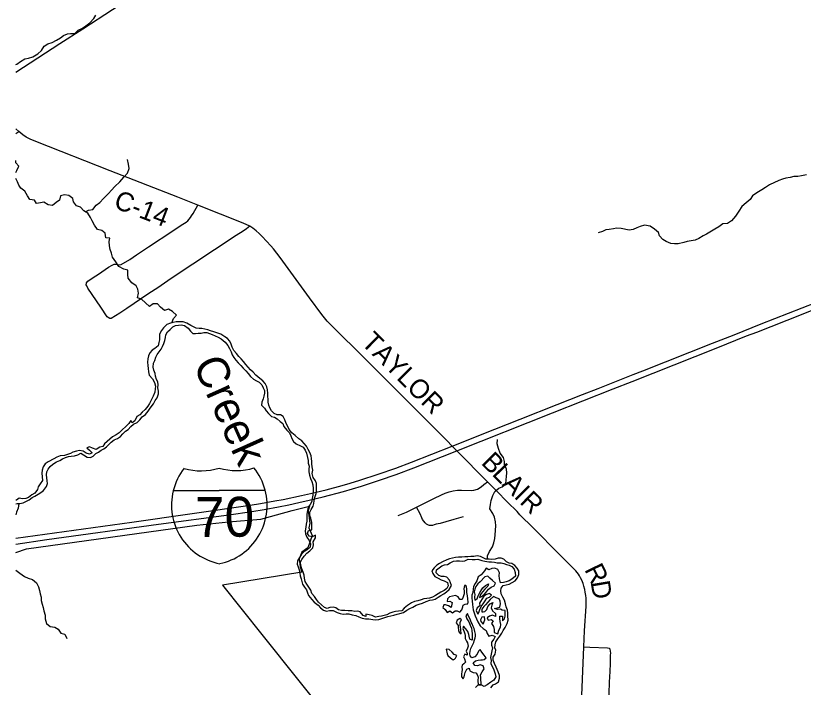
# Model space of a CAD drawing. Extents: x 114843 to 284848, y 317643 to 566895.
# Drawn here: x 114843 to 127204, y 384376 to 394917 of the extents above; entities that cross this region are included whole.
import ezdxf

# ---------------------------------------------------------------- set-up
doc = ezdxf.new("R2010")
doc.units = 0
for name, color, linetype in [('GM_X_Corporation', 7, 'Continuous'), ('GM_X_County_Road', 7, 'Continuous'), ('GM_X_County_Road_Text', 7, 'Continuous'), ('GM_X_Interstate_Location', 7, 'Continuous'), ('GM_X_Interstate_Route', 7, 'Continuous'), ('GM_X_Interstate_Shield', 7, 'Continuous'), ('GM_X_Major_River', 7, 'Continuous'), ('GM_X_Major_River_Text', 7, 'Continuous'), ('GM_X_Minor_Lake', 7, 'Continuous'), ('GM_X_Minor_River', 7, 'Continuous'), ('GM_X_Township_Road', 7, 'Continuous')]:
    doc.layers.add(name, color=color, linetype=linetype)

msp = doc.modelspace()

# ---------------------------------------------------------------- linework, layer by layer
at = {"layer": 'GM_X_Corporation'}
msp.add_lwpolyline([(114843, 386490), (115013, 386549), (117687, 386922), (118185, 386971), (118689, 387015), (119180, 387148), (119453, 387216), (119431, 387149), (119458, 386954), (119444, 386879), (119495, 386757), (119430, 386567), (119336, 386495), (119292, 386394), (119309, 386265), (119336, 386184), (118089, 385981), (118705, 385204), (119847, 383776)], dxfattribs=at)
at = {"layer": 'GM_X_County_Road'}
msp.add_line((114891, 393098), (114843, 393144), dxfattribs=at)
for points in [[(114843, 394030), (115537, 394481), (115896, 394713), (116363, 395017), (116608, 395180), (117070, 395482), (117905, 396014), (118844, 396617), (119342, 396934), (119699, 397166), (120059, 397395), (120571, 397725), (121846, 398557), (122838, 399201), (123440, 399595), (124015, 399975), (124071, 400009), (124123, 400049), (124177, 400087), (124205, 400104), (124322, 400169)], [(118515, 391612), (118461, 391640), (118386, 391672), (118055, 391803), (117699, 391946), (117386, 392070), (116324, 392482), (115157, 392941), (115067, 392979), (115037, 392993), (115008, 393009), (114954, 393046), (114891, 393098)], [(122246, 387600), (121765, 388088), (121694, 388161), (121607, 388250), (121545, 388311), (121076, 388785), (120288, 389572), (119845, 390009), (119731, 390124), (119687, 390175), (119646, 390227), (119452, 390491), (118991, 391123), (118887, 391256), (118845, 391306), (118780, 391380), (118713, 391452), (118666, 391498), (118618, 391542), (118592, 391563), (118565, 391581), (118515, 391612)], [(123758, 385008), (123770, 385259), (123794, 385651), (123796, 385717), (123794, 385777), (123791, 385815), (123782, 385871), (123774, 385911), (123759, 385965), (123747, 386006), (123726, 386057), (123708, 386096), (123692, 386124), (123674, 386151), (123633, 386202), (123473, 386366), (123264, 386574), (123080, 386761), (123010, 386829), (122965, 386877), (122757, 387085), (122712, 387133), (122562, 387280), (122388, 387458), (122246, 387600)], [(123665, 382836), (123691, 383364), (123758, 385008)]]:
    msp.add_lwpolyline(points, dxfattribs=at)
at = {"layer": 'GM_X_Interstate_Route'}
for points in [[(114843, 386624), (115332, 386693), (117085, 386935), (118190, 387084), (118547, 387136), (118741, 387168), (118967, 387209), (119128, 387241), (119288, 387276), (119448, 387311), (119671, 387365), (119988, 387450), (120271, 387534), (120552, 387625), (120816, 387718), (121094, 387822), (121765, 388088), (123267, 388684), (124218, 389058), (124517, 389177), (125835, 389697), (126314, 389890), (126476, 389950), (127177, 390227), (127765, 390461)], [(114843, 386718), (116664, 386970), (118524, 387234), (118686, 387261), (118912, 387300), (119041, 387325), (119330, 387384), (119471, 387416), (119713, 387477), (119966, 387545), (120092, 387581), (120246, 387628), (120530, 387720), (120809, 387816), (121054, 387908), (121694, 388161), (122363, 388425), (122762, 388584), (123343, 388812), (123739, 388970), (123983, 389065), (124196, 389151), (124532, 389283), (124686, 389343), (125782, 389777), (126118, 389909), (126545, 390079), (127400, 390416)]]:
    msp.add_lwpolyline(points, dxfattribs=at)
at = {"layer": 'GM_X_Interstate_Shield'}
for p, q in [((117316, 387460), (118758, 387470)), ((118758, 387470), (117316, 387460)), ((118758, 387470), (117316, 387460))]:
    msp.add_line(p, q, dxfattribs=at)
for centre, start, end in [((118226, 387236), 142.0801, 166.2178), ((117754, 388711), 253.4202, 287.4021), ((118302, 388715), 253.4202, 287.4021), ((117851, 387234), 14.6045, 38.7422), ((118226, 387236), 166.2178, 258.8742), ((117851, 387234), 281.9481, 14.6045)]:
    msp.add_arc(centre, 938, start, end, dxfattribs=at)
at = {"layer": 'GM_X_Major_River'}
msp.add_line((122103, 384414), (122149, 384412), dxfattribs=at)
for points in [[(119355, 386182), (119335, 386236), (119320, 386288), (119312, 386338), (119336, 386383), (119370, 386435), (119414, 386479), (119458, 386517), (119504, 386565), (119518, 386609), (119510, 386657), (119550, 386721), (119546, 386761), (119494, 386737), (119448, 386747), (119422, 386791), (119440, 386837), (119492, 386849), (119492, 386961), (119476, 387028), (119458, 387074), (119460, 387122), (119482, 387166), (119512, 387216), (119520, 387262), (119528, 387304), (119540, 387354), (119556, 387416), (119564, 387468), (119566, 387516), (119562, 387572), (119546, 387616), (119510, 387669), (119494, 387729), (119504, 387785), (119498, 387837), (119493, 387881), (119489, 387921), (119485, 387969), (119479, 388011), (119459, 388059), (119435, 388107), (119407, 388159), (119371, 388203), (119333, 388244), (119289, 388274), (119227, 388330), (119179, 388368), (119137, 388420), (119117, 388460), (119087, 388518), (119067, 388572), (119039, 388624), (118997, 388650), (118949, 388654), (118897, 388673), (118859, 388715), (118831, 388761), (118816, 388803), (118806, 388849), (118804, 388895), (118802, 388943), (118800, 388993), (118794, 389043), (118782, 389093), (118756, 389145), (118720, 389187), (118676, 389222), (118610, 389276), (118570, 389320), (118528, 389360), (118490, 389402), (118454, 389444), (118416, 389488), (118380, 389530), (118344, 389570), (118306, 389614), (118268, 389662), (118240, 389713), (118222, 389761), (118203, 389807), (118167, 389849), (118123, 389877), (118061, 389917), (117999, 389941), (117951, 389955), (117901, 389971), (117857, 389985), (117811, 389997), (117765, 390005), (117723, 390009), (117677, 390011), (117633, 390032), (117591, 390056), (117531, 390090), (117471, 390110), (117411, 390110), (117361, 390112), (117315, 390102), (117273, 390092), (117217, 390068)], [(117217, 390068), (117161, 390018), (117129, 389976), (117101, 389916), (117097, 389872), (117097, 389830), (117091, 389786), (117079, 389735), (117025, 389693), (116985, 389669), (116949, 389627), (116925, 389579), (116915, 389529), (116911, 389479), (116915, 389425), (116923, 389377), (116927, 389325), (116939, 389275), (116991, 389215), (117019, 389161), (117037, 389102), (117031, 389058), (117025, 389010), (116999, 388946), (116941, 388830), (116915, 388788), (116877, 388734), (116829, 388692), (116791, 388653), (116745, 388626), (116711, 388560), (116669, 388525), (116651, 388562), (116618, 388518), (116576, 388476), (116510, 388414), (116468, 388368), (116418, 388336), (116360, 388308), (116320, 388268), (116276, 388234), (116234, 388198), (116208, 388156), (116163, 388144), (116107, 388107), (116049, 388130), (116003, 388150), (115959, 388132), (116003, 388100), (116045, 388055), (116001, 388033), (115949, 388051), (115901, 388080), (115843, 388094), (115797, 388080), (115741, 388064), (115701, 388044), (115653, 388028), (115611, 388016), (115539, 388008), (115489, 387988), (115441, 387964), (115353, 387912), (115303, 387884), (115271, 387838), (115259, 387783), (115255, 387735), (115257, 387679), (115261, 387621), (115229, 387571), (115193, 387523), (115185, 387481), (115143, 387423), (115095, 387395), (115045, 387357), (114999, 387339), (114951, 387333), (114897, 387343), (114857, 387315), (114843, 387311)], [(114843, 387256), (114863, 387261), (114905, 387263), (114961, 387273), (115011, 387295), (115053, 387319), (115101, 387353), (115145, 387377), (115193, 387405), (115235, 387433), (115281, 387467), (115325, 387527), (115339, 387573), (115337, 387617), (115333, 387663), (115325, 387709), (115329, 387755), (115353, 387797), (115385, 387840), (115427, 387878), (115483, 387914), (115533, 387936), (115575, 387960), (115623, 387982), (115669, 387996), (115715, 388002), (115763, 388010), (115817, 388026), (115863, 388052), (115909, 388023), (115966, 387989), (116016, 387983), (116058, 388003), (116102, 388045), (116144, 388067), (116186, 388099), (116228, 388119), (116270, 388151), (116342, 388224), (116388, 388258), (116440, 388280), (116486, 388312), (116522, 388356), (116566, 388396), (116610, 388424), (116652, 388468), (116694, 388504), (116748, 388530), (116792, 388576), (116826, 388622), (116882, 388660), (116924, 388712), (116952, 388756), (117006, 388824), (117031, 388876), (117063, 388920), (117085, 388982), (117083, 389022), (117071, 389074), (117081, 389122), (117075, 389169), (117051, 389209), (117039, 389259), (117031, 389303), (117011, 389351), (116999, 389399), (117005, 389461), (117025, 389507), (117043, 389555), (117063, 389599), (117093, 389641), (117127, 389683), (117149, 389725), (117167, 389773), (117183, 389818), (117193, 389868), (117199, 389910), (117225, 389956), (117267, 389992)], [(117267, 389992), (117311, 390034)], [(117311, 390034), (117351, 390056), (117399, 390060), (117441, 390064), (117491, 390056), (117551, 390012), (117585, 389967), (117623, 389927), (117667, 389931), (117709, 389933), (117751, 389933), (117795, 389945), (117841, 389943), (117883, 389927), (117927, 389913), (117971, 389893), (118019, 389873), (118065, 389843), (118129, 389791), (118170, 389741), (118196, 389693), (118224, 389643), (118242, 389594), (118264, 389550), (118296, 389510), (118332, 389468), (118374, 389426), (118414, 389384), (118454, 389344), (118492, 389302), (118530, 389256), (118576, 389212), (118622, 389188), (118664, 389163), (118704, 389123), (118728, 389077), (118746, 389035), (118746, 388991), (118738, 388945), (118726, 388903), (118704, 388849), (118702, 388803), (118746, 388757), (118773, 388715), (118811, 388673), (118855, 388628), (118903, 388618), (118945, 388592), (118991, 388546), (119035, 388514), (119051, 388468), (119097, 388410), (119141, 388372), (119159, 388324), (119175, 388282), (119201, 388234), (119243, 388198), (119311, 388167), (119353, 388143), (119387, 388099), (119405, 388049), (119421, 387985), (119431, 387937), (119435, 387895), (119447, 387849), (119445, 387801), (119442, 387757), (119452, 387703), (119472, 387655), (119490, 387606), (119508, 387556), (119514, 387496), (119510, 387442), (119506, 387392), (119498, 387340), (119488, 387294), (119464, 387246), (119432, 387202), (119420, 387148), (119412, 387094), (119412, 387032), (119410, 386983), (119404, 386935), (119396, 386891), (119384, 386833), (119392, 386785), (119412, 386733), (119450, 386679), (119472, 386627), (119464, 386577), (119416, 386533), (119370, 386509), (119330, 386463), (119296, 386411), (119268, 386363), (119258, 386310), (119278, 386268), (119291, 386218), (119301, 386168), (119307, 386124)], [(122460, 385930), (122494, 385974), (122540, 385986), (122586, 385994), (122636, 386018), (122682, 386048), (122718, 386096), (122742, 386146), (122740, 386202), (122714, 386246), (122676, 386289), (122628, 386317), (122586, 386323), (122544, 386343), (122504, 386385), (122462, 386401), (122414, 386401), (122366, 386389), (122318, 386379), (122274, 386387), (122224, 386389), (122178, 386405), (122136, 386431), (122084, 386437), (122032, 386431), (121986, 386427), (121938, 386425), (121890, 386421), (121846, 386419), (121792, 386417), (121748, 386415), (121696, 386401), (121652, 386393), (121608, 386375), (121544, 386343), (121496, 386321), (121452, 386291), (121412, 386251), (121376, 386205), (121388, 386163), (121422, 386117), (121474, 386087), (121522, 386063), (121570, 386049), (121618, 386019), (121632, 385967), (121610, 385924), (121566, 385894), (121518, 385866), (121476, 385842), (121430, 385814), (121386, 385790), (121340, 385774), (121294, 385768), (121248, 385764), (121206, 385750), (121154, 385734), (121100, 385722), (121054, 385700), (120994, 385660), (120940, 385618), (120902, 385576), (120852, 385572), (120802, 385564), (120762, 385554), (120714, 385538), (120666, 385514), (120624, 385502), (120582, 385494), (120542, 385484), (120488, 385478), (120438, 385500), (120388, 385514), (120340, 385525), (120340, 385484), (120294, 385503), (120249, 385561), (120207, 385571), (120165, 385567), (120121, 385575), (120059, 385577), (120011, 385579), (119957, 385579), (119911, 385591), (119869, 385621), (119823, 385633), (119775, 385629), (119733, 385611), (119687, 385629), (119641, 385671), (119595, 385709), (119565, 385753), (119531, 385799), (119493, 385846), (119473, 385898), (119445, 385946), (119411, 385992), (119387, 386038), (119375, 386088), (119369, 386136), (119355, 386182)], [(119307, 386124), (119323, 386078), (119333, 386034), (119345, 385992), (119377, 385948), (119409, 385904), (119425, 385860), (119437, 385818), (119491, 385755), (119529, 385713), (119589, 385665), (119625, 385621), (119673, 385585), (119719, 385569), (119767, 385579), (119823, 385579), (119887, 385549), (119937, 385533), (119985, 385525), (120029, 385529), (120073, 385527), (120123, 385515), (120183, 385501), (120230, 385483), (120282, 385460), (120334, 385450), (120384, 385448), (120448, 385438), (120490, 385436), (120544, 385442), (120588, 385456), (120634, 385472), (120682, 385488), (120778, 385508), (120830, 385522), (120870, 385532), (120928, 385552), (120980, 385586), (121030, 385612), (121076, 385634), (121128, 385662), (121174, 385682), (121230, 385698), (121284, 385722), (121342, 385742), (121382, 385750), (121424, 385760), (121474, 385792), (121516, 385814), (121560, 385844), (121602, 385872), (121648, 385908), (121682, 385973), (121668, 386015), (121652, 386059), (121612, 386105), (121568, 386113), (121526, 386113), (121482, 386129), (121444, 386173), (121448, 386217), (121490, 386253), (121530, 386283), (121574, 386299), (121620, 386305), (121664, 386329), (121712, 386355), (121760, 386359), (121806, 386359), (121852, 386355), (121894, 386363), (121944, 386385), (122008, 386381), (122054, 386379), (122096, 386389), (122160, 386365), (122206, 386353), (122268, 386345), (122310, 386345), (122356, 386337), (122402, 386331), (122462, 386327), (122504, 386321), (122546, 386305), (122588, 386295), (122632, 386271), (122666, 386230), (122680, 386178), (122686, 386120), (122632, 386074), (122586, 386046), (122542, 386030), (122498, 386022), (122452, 386016), (122434, 386078), (122432, 386132), (122438, 386174), (122412, 386223), (122364, 386247), (122314, 386239), (122270, 386219)], [(122270, 386219), (122228, 386243), (122202, 386201), (122148, 386143), (122104, 386109), (122078, 386048), (122054, 386006), (122028, 385960), (122022, 385914), (122016, 385864), (122000, 385822), (122000, 385774), (122006, 385732), (122010, 385676), (122020, 385632), (122024, 385592), (122036, 385546), (122056, 385496), (122077, 385449), (122097, 385403), (122131, 385341), (122181, 385299), (122229, 385267), (122241, 385221), (122269, 385179), (122319, 385191), (122369, 385173), (122345, 385129), (122313, 385083), (122311, 385037), (122325, 384993), (122317, 384949), (122305, 384894), (122297, 384844), (122303, 384796), (122301, 384750), (122349, 384650), (122367, 384588), (122381, 384542), (122349, 384486), (122301, 384454), (122241, 384412), (122195, 384390), (122149, 384412), (122103, 384414), (122059, 384374)], [(122376, 386008), (122328, 386050), (122286, 386088), (122252, 386122), (122208, 386108), (122132, 386032), (122094, 386002), (122064, 385958), (122050, 385914), (122036, 385872), (122050, 385832), (122044, 385788), (122050, 385744), (122066, 385753)], [(122066, 385753), (122088, 385766), (122104, 385812), (122122, 385852), (122142, 385892), (122176, 385936), (122214, 385972), (122262, 385998), (122252, 385962), (122204, 385916), (122168, 385874), (122136, 385830), (122124, 385786), (122156, 385800), (122196, 385834), (122232, 385874), (122262, 385914), (122306, 385946), (122352, 385966), (122376, 386008)], [(122301, 384368), (122335, 384414), (122375, 384432), (122421, 384462), (122435, 384516), (122435, 384560), (122415, 384620), (122383, 384690), (122357, 384748), (122339, 384802), (122339, 384850), (122369, 384896), (122377, 384957), (122365, 384997), (122367, 385043), (122381, 385087), (122409, 385135), (122441, 385177), (122475, 385227), (122495, 385269), (122525, 385315), (122555, 385377), (122573, 385431), (122567, 385495), (122569, 385539), (122563, 385585), (122539, 385638), (122533, 385686), (122517, 385742), (122488, 385792), (122464, 385844), (122456, 385890), (122460, 385930)], [(122289, 385838), (122278, 385846), (122232, 385830), (122192, 385806), (122166, 385762), (122136, 385722), (122122, 385696), (122126, 385656), (122084, 385624), (122068, 385582), (122098, 385524)], [(122098, 385524), (122114, 385550), (122130, 385598), (122148, 385646), (122180, 385688), (122212, 385732), (122236, 385772), (122280, 385788), (122310, 385822), (122289, 385838)], [(122409, 385214), (122427, 385273), (122451, 385317), (122459, 385361), (122449, 385409), (122439, 385453), (122439, 385493), (122481, 385491), (122485, 385465), (122485, 385417), (122517, 385449), (122523, 385491), (122523, 385533), (122527, 385583), (122477, 385588), (122451, 385600), (122407, 385596), (122359, 385614), (122439, 385634), (122451, 385684), (122445, 385726), (122430, 385766), (122386, 385780), (122340, 385798), (122292, 385756), (122254, 385712), (122216, 385672), (122192, 385644), (122160, 385602), (122160, 385558), (122181, 385560)], [(122181, 385560), (122206, 385564), (122240, 385598), (122254, 385644), (122290, 385686), (122334, 385706), (122316, 385662), (122303, 385622), (122325, 385578), (122371, 385533), (122375, 385489), (122327, 385507), (122281, 385491), (122241, 385467), (122259, 385431), (122303, 385441), (122339, 385417), (122311, 385375), (122343, 385329), (122353, 385285), (122353, 385237), (122409, 385214)], [(122149, 384412), (122141, 384526), (122139, 384570), (122165, 384616), (122197, 384666), (122181, 384710), (122135, 384728), (122089, 384714), (122047, 384716), (122025, 384758), (122061, 384792), (122101, 384802), (122141, 384806), (122169, 384808), (122197, 384810), (122225, 384838), (122193, 384878), (122159, 384927), (122133, 384971), (122105, 384941), (122085, 384895), (122047, 384855), (122003, 384837), (121975, 384871), (121973, 384899), (121977, 384943), (121985, 384985), (122015, 385035), (122035, 385079), (122041, 385105), (122055, 385151), (122059, 385179), (122057, 385209), (122051, 385253), (122039, 385299), (122023, 385329), (122009, 385373), (121993, 385399), (121974, 385444), (121948, 385492), (121934, 385532), (121908, 385496), (121924, 385452), (121954, 385401), (121975, 385349), (121995, 385303), (122003, 385261), (122009, 385213), (122009, 385161), (122007, 385115), (121983, 385127)], [(122150, 385457), (122139, 385433), (122145, 385407), (122179, 385367)], [(122179, 385367), (122205, 385435), (122203, 385481), (122159, 385477), (122150, 385457)], [(121983, 385127), (121971, 385133), (121961, 385179), (121955, 385205), (121941, 385249), (121907, 385291), (121872, 385337), (121859, 385297), (121881, 385245), (121891, 385215), (121895, 385189), (121899, 385143), (121919, 385101), (121935, 385071), (121945, 385019), (121935, 384991), (121911, 384945), (121929, 384905), (121931, 384879), (121891, 384893), (121871, 384851), (121887, 384823), (121901, 384772), (121879, 384744), (121851, 384724), (121847, 384698), (121849, 384652), (121847, 384624), (121841, 384580), (121841, 384540), (121867, 384510), (121883, 384540), (121889, 384566), (121897, 384608), (121923, 384658), (121959, 384678), (121971, 384636), (122021, 384610), (122065, 384604), (122087, 384578), (122099, 384534), (122097, 384484), (122103, 384414)]]:
    msp.add_lwpolyline(points, dxfattribs=at)
at = {"layer": 'GM_X_Minor_Lake'}
for points in [[(121926, 385684), (121940, 385686), (121942, 385714), (121938, 385762), (121936, 385810), (121930, 385836), (121926, 385864), (121922, 385912), (121920, 385956), (121892, 385976), (121880, 385948), (121878, 385922), (121882, 385882), (121884, 385842), (121866, 385796), (121852, 385754), (121812, 385756), (121790, 385796), (121748, 385818), (121698, 385804), (121650, 385796), (121622, 385762), (121614, 385720), (121658, 385728), (121692, 385708), (121678, 385630)], [(121678, 385630), (121636, 385652), (121590, 385668), (121564, 385672), (121548, 385628), (121582, 385594), (121614, 385550), (121658, 385574), (121698, 385542), (121740, 385576), (121774, 385574), (121814, 385556), (121846, 385592), (121860, 385638), (121868, 385664), (121898, 385680), (121926, 385684)], [(121797, 385443), (121774, 385428), (121758, 385386), (121786, 385345), (121788, 385317), (121792, 385269), (121801, 385243), (121833, 385215)], [(121833, 385215), (121831, 385279), (121822, 385323), (121818, 385349), (121820, 385396), (121842, 385436), (121814, 385454), (121797, 385443)], [(121601, 384973), (121617, 384899), (121625, 384873), (121667, 384839), (121711, 384807), (121729, 384819)], [(121729, 384819), (121747, 384831), (121769, 384877), (121727, 384891), (121691, 384929), (121647, 384967), (121601, 384973)]]:
    msp.add_lwpolyline(points, dxfattribs=at)
at = {"layer": 'GM_X_Minor_River'}
for points in [[(114843, 394149), (114859, 394158), (114919, 394200), (114987, 394238), (115045, 394252), (115113, 394272), (115189, 394320), (115245, 394372), (115291, 394438), (115347, 394476), (115413, 394498), (115481, 394534), (115543, 394568), (115593, 394608), (115655, 394632), (115705, 394636), (115773, 394640), (115823, 394690), (115889, 394724), (115941, 394756), (116005, 394806), (116069, 394872), (116101, 394924)], [(114843, 392454), (114862, 392487), (114890, 392557), (114846, 392609), (114843, 392642)], [(115937, 391839), (115987, 391864), (116051, 391876), (116105, 391946), (116163, 391986), (116223, 392048), (116297, 392124), (116345, 392178), (116401, 392236), (116477, 392312), (116541, 392384), (116597, 392448), (116621, 392520), (116613, 392588), (116597, 392658)], [(117295, 390097), (117319, 390164), (117367, 390218), (117303, 390276), (117241, 390312), (117177, 390288), (117117, 390340), (117069, 390397), (117000, 390393), (116940, 390353), (116880, 390411), (116818, 390469), (116752, 390491), (116772, 390563), (116762, 390623), (116734, 390677), (116666, 390723), (116606, 390799), (116602, 390854), (116600, 390922), (116540, 390940), (116462, 390982), (116414, 391054), (116360, 391126), (116348, 391192), (116326, 391248), (116314, 391304), (116311, 391375), (116319, 391425), (116257, 391431), (116247, 391505), (116195, 391547), (116125, 391563), (116077, 391627), (116045, 391697), (116019, 391749), (115975, 391816), (115913, 391854), (115861, 391910), (115799, 391934), (115749, 391994), (115737, 392050), (115679, 392096), (115609, 392108), (115547, 392088), (115531, 392024), (115475, 391986), (115421, 391938), (115351, 391948), (115283, 391988), (115233, 391978), (115170, 391968), (115138, 392022), (115064, 392030), (115028, 392089), (114984, 392161), (114922, 392209), (114894, 392259), (114870, 392309), (114843, 392361)], [(127253, 392418), (127175, 392404), (127119, 392394), (127057, 392392), (126999, 392380), (126933, 392368), (126877, 392352), (126821, 392332), (126674, 392260), (126612, 392220), (126552, 392184), (126478, 392138), (126410, 392088), (126370, 392034), (126308, 391978), (126240, 391920), (126194, 391850), (126140, 391771), (126079, 391697), (126014, 391655), (125944, 391649), (125880, 391605), (125816, 391569), (125736, 391519), (125686, 391489), (125634, 391461), (125564, 391421), (125510, 391395), (125444, 391385), (125384, 391375), (125332, 391359), (125240, 391339), (125182, 391337), (125126, 391341), (125052, 391373), (125000, 391403), (124946, 391461), (124932, 391516), (124870, 391568), (124802, 391616), (124710, 391628), (124646, 391606), (124594, 391586), (124536, 391560), (124472, 391552), (124348, 391576), (124274, 391580), (124224, 391570), (124156, 391560), (124107, 391554), (124055, 391528), (123987, 391510)], [(122246, 386388), (122250, 386439), (122278, 386509), (122326, 386581), (122346, 386645), (122362, 386713), (122368, 386771), (122380, 386908), (122376, 386972), (122358, 387046), (122329, 387102), (122283, 387176), (122293, 387244), (122307, 387306), (122333, 387388), (122361, 387449), (122427, 387503), (122477, 387521), (122535, 387569), (122543, 387633), (122547, 387685), (122549, 387741), (122547, 387797), (122515, 387871), (122513, 387921), (122497, 387981), (122445, 388051), (122421, 388124), (122401, 388196), (122403, 388264)], [(114889, 387262), (114883, 387185), (114853, 387123), (114843, 387083)], [(114843, 386213), (114906, 386167), (114980, 386117), (115036, 386087), (115108, 386069), (115170, 386013), (115198, 385950), (115215, 385896), (115227, 385842), (115241, 385792), (115243, 385740), (115259, 385678), (115271, 385628), (115285, 385576), (115305, 385508), (115307, 385452), (115325, 385379), (115381, 385329), (115455, 385321), (115509, 385287), (115553, 385225), (115615, 385207), (115645, 385141)]]:
    msp.add_lwpolyline(points, dxfattribs=at)
at = {"layer": 'GM_X_Township_Road'}
msp.add_line((114843, 393071), (114891, 393098), dxfattribs=at)
for points in [[(115957, 390677), (115950, 390694), (115953, 390719), (115956, 390726), (115976, 390752), (116057, 390806), (116140, 390858), (116193, 390896), (116301, 390969), (116357, 391003), (116387, 391018), (116415, 391019), (116438, 391012), (116476, 391007), (116497, 391012), (116632, 391092), (116739, 391165), (116928, 391291), (117309, 391541), (117441, 391628), (117468, 391643), (117494, 391660), (117519, 391679), (117544, 391699), (117584, 391748), (117603, 391774), (117628, 391814), (117699, 391946)], [(118515, 391612), (118464, 391573), (118412, 391536), (118304, 391467), (117285, 390792), (117071, 390647), (116934, 390559), (116587, 390319), (116477, 390249), (116342, 390167), (116337, 390167)], [(116337, 390167), (116321, 390167), (116293, 390179), (116279, 390190), (116181, 390342), (115975, 390643), (115957, 390677)], [(121133, 387203), (121408, 387340), (121526, 387397), (121586, 387424), (121647, 387446), (121711, 387460), (121776, 387468), (121841, 387469), (122003, 387466), (122035, 387468), (122089, 387483), (122148, 387522), (122191, 387560), (122246, 387600)], [(120845, 387071), (120898, 387092), (120975, 387126), (121133, 387203)], [(121866, 387050), (121721, 387009), (121594, 386975), (121504, 386949), (121473, 386941), (121443, 386935), (121413, 386924), (121383, 386917), (121352, 386916), (121339, 386917), (121321, 386921), (121291, 386934), (121267, 386955), (121246, 386981), (121229, 387008), (121215, 387037), (121190, 387096), (121133, 387203)], [(123758, 385008), (123852, 385007), (124132, 384995), (124156, 384990), (124164, 384983)], [(124095, 382818), (124108, 383123), (124117, 383296), (124126, 383578), (124134, 383642), (124135, 383666), (124134, 383708), (124137, 383805), (124151, 384098), (124163, 384457), (124171, 384624), (124179, 384750), (124176, 384815), (124181, 384880), (124183, 384913), (124180, 384945), (124171, 384976), (124164, 384983)]]:
    msp.add_lwpolyline(points, dxfattribs=at)

# ---------------------------------------------------------------- texts
at = {"layer": 'GM_X_County_Road_Text'}
for s, rotation, p in [('C-14', 338.9286, (116364, 391909)), ('TAYLOR', 315.0522, (120254, 389772)), ('B', 314.5281, (122134, 387889)), ('L', 314.5329, (122307, 387713)), ('A', 314.5329, (122464, 387553)), ('I', 314.5972, (122650, 387364)), ('R', 315.3893, (122739, 387274)), ('R', 296.0024, (123764, 386226)), ('D', 279.594, (123866, 386026))]:
    msp.add_text(s, height=300, rotation=rotation, dxfattribs=at).set_placement(p)
at = {"layer": 'GM_X_Interstate_Location'}
for s, p in [('.', (118040, 387066)), ('-', (118040, 387066)), (',', (118040, 387066)), ('70', (117837, 386857))]:
    msp.add_text(s, height=1, rotation=0.4112, dxfattribs=at).set_placement(p)
at = {"layer": 'GM_X_Interstate_Shield'}
msp.add_text('70', height=625, rotation=0.4112, dxfattribs=at).set_placement((117658, 386735))
at = {"layer": 'GM_X_Major_River_Text'}
msp.add_text('Creek', height=500.1, rotation=294.0955, dxfattribs=at).set_placement((117620, 389447))

doc.saveas('drawing.dxf')
